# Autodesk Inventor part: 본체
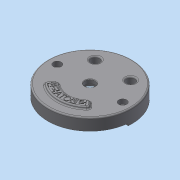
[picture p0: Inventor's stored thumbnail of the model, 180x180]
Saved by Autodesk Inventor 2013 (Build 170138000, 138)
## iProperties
Created: 2015-04
Part Number: 본체
Material: 일반
Document SubType Name: Modeling
Designer: Administrator
Density: 1 g/cm^3
Author: Administrator
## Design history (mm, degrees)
sketch "스케치1"
  geometry: C1 r 95 at (0, 0); 1 further point
  constraints: 1 centre point, 1 coincident
  dimensions: "d0" = 190 diameter of C1
extrude "돌출1" new body sketch "스케치1" distance "d1" = 32; taper "d2" = 0 deg
feature "쉘1" dims "d3" = 14, "d4" = 5
sketch "스케치2"
  geometry: C1 r 90 at (0, 0) reference; C2 r 35 at (0, 0)
  constraints: 1 centre point, 1 coincident
  dimensions: "d5" = 70 diameter of C2
extrude "돌출2" join sketch "스케치2" distance "d6" = 10; taper "d7" = -10 deg
sketch "스케치3"
  geometry: C1 r 35 at (0, 0) reference; A1 r 41 centre (0, -19) between (-40.794, -14.9) and (40.794, -14.9); A2 r 59 centre (0, -19) between (-58.704, -13.1) and (58.704, -13.1); A3 r 9 centre (-49.749, -14) between (-40.794, -14.9) and (-58.704, -13.1); A4 r 9 centre (49.749, -14) between (58.704, -13.1) and (40.794, -14.9)
  constraints: 8 point on circle, 4 centre point, 2 tangent, 1 coincident, 1 vertical alignment
  dimensions: "d8" = 82 diameter of A1; "d9" = 19 distance of A1.centre C1.centre; "d10" = 118 diameter of A2; "d11" = 18 diameter of A3; "d12" = 18 diameter of A4; "d13" = 14 vertical distance of C1.centre A3.centre; "d14" = 14 vertical distance of C1.centre A4.centre
extrude "돌출3" cut sketch "스케치3" distance "d15" = 7; taper "d16" = 0 deg
sketch "스케치4"
  geometry: L1 (-89.196, 12)-(-40.249, 12); L2 (40.249, 12)-(89.196, 12); C1 r 35 at (0, 0) reference; A1 r 90 centre (0, 0) between (89.196, 12) and (-89.196, 12) reference; A2 r 42 centre (0, 0) between (40.249, 12) and (-40.249, 12)
  constraints: 4 end point, 4 point on circle, 2 horizontal, 1 centre point, 1 coincident
  dimensions: "d17" = 84 diameter of A2; "d19" = 12 distance from line of C1.centre L1; "d20" = 12 distance from line of C1.centre L2
extrude "돌출4" cut sketch "스케치4" distance "d21" = 7; taper "d22" = 0 deg
fillet "모깎기1" dims "d23" = 10
sketch "스케치5"
  geometry: C1 r 95 at (0, 0) reference; C2 r 15 at (-40, 52); C3 r 9 at (-74, 0)
  constraints: 2 centre point, 1 horizontal alignment
  dimensions: "d24" = 30 diameter of C2; "d25" = 18 diameter of C3; "d26" = 52 vertical distance of C1.centre C2.centre; "d27" = 40 horizontal distance of C1.centre C2.centre; "d28" = 74 distance of C1.centre C3.centre
extrude "돌출5" join sketch "스케치5" distance "d29" = 32; taper "d30" = 0 deg
sketch "스케치6"
  geometry: C1 r 15 at (0, 0) reference; C2 r 10 at (0, 0); 1 further point
  constraints: 1 centre point, 1 coincident
  dimensions: "d31" = 20 diameter of C2
extrude "돌출6" cut sketch "스케치6" stored distance "d32" = 32; taper "d33" = 0 deg
sketch "스케치7"
  geometry: C1 r 9 at (-74, 0) reference
hole "구멍1" sketch "스케치7" at (-74, 0) diameter "d34" = 11; stored, may be unused: countersink angle "d38" = 90 deg, drill point angle "d40" = 118 deg; dims "d35" = 6, "d36" = 18, "d37" = 11, "d39" = 8
sketch "스케치8"
  geometry: L1 (-20, 6)-(20, 6); L2 (20, 6)-(20, -6); L3 (20, -6)-(-20, -6); L4 (-20, -6)-(-20, 6); L5 (-86, 20)-(-74, 20); L6 (-74, 20)-(-74, -20); L7 (-74, -20)-(-86, -20); L8 (-86, -20)-(-86, 20); C1 r 10 at (0, 0) reference; C2 r 10 at (-80, 0) reference; C3 r 15 at (-80, 0) reference; 5 further points
  constraints: 16 end point, 4 midpoint, 4 parallel, 2 horizontal, 2 horizontal alignment, 2 perpendicular, 2 vertical alignment
  dimensions: "d41" = 12 distance of L3.end L1.start; "d43" = 12 distance of L5.start L5.end; "d44" = 40 distance of L1.start L1.end; "d45" = 40 distance of L5.end L6.end
extrude "돌출7" cut sketch "스케치8" distance "d46" = 3; taper "d47" = 0 deg
sketch "스케치9"
  geometry: C1 r 33.237 at (0, 0) reference
hole "구멍2" sketch "스케치9" at (0, 0) diameter "d48" = 23; stored, may be unused: countersink angle "d52" = 90 deg, drill point angle "d54" = 118 deg; dims "d49" = 6, "d50" = 50, "d51" = 15, "d53" = 8
chamfer "모따기1" distance "d55" = 1; stored, may be unused: second distance "d56" = 2, angle "d57" = 45 deg
fillet "모깎기2" dims "d58" = 3
node "작업 평면1"
sketch "스케치10"
  geometry: L1 (-89.658, -7.844)-(-101.855, -8.911); L2 (89.658, -7.844)-(101.855, -8.911); L3 (-74, 0)-(74, 0); C1 r 95 at (0, 0) reference; C2 r 10 at (40, 52) reference; C3 r 10 at (-40, 52) reference; C4 r 15 at (40, 52) reference; C5 r 15 at (-40, 52) reference; C6 r 5.5 at (74, 0) reference; C7 r 9 at (74, 0) reference; C8 r 5.5 at (-74, 0) reference; C9 r 9 at (-74, 0) reference; A1 r 90 centre (0, 0) between (-89.658, -7.844) and (89.658, -7.844) reference; A2 r 102.244 centre (0, 0) between (-101.855, -8.911) and (101.855, -8.911); A3 r 90 centre (0, 0) between (-89.658, -7.844) and (89.658, -7.844); 1 further point
  constraints: 6 end point, 6 point on circle, 2 centre point, 2 coincident, 1 concentric, 1 horizontal
  dimensions: "d62" = 204.48899 diameter of A2; "d63" = 5 deg angle of L1 L3; "d64" = 5 deg angle of L2 L3; "d65" = 7.84402 vertical distance of L1.start C8.centre; "d66" = 7.84402 vertical distance of L2.start C6.centre
extrude "돌출8" cut sketch "스케치10" distance "d67" = 5; taper "d68" = 0 deg
fillet "모깎기3" dims "d69" = 3
sketch "스케치11"
  geometry: L1 (-72, 0)-(0, 0); L2 (36.062, -36.062)-(50.912, -50.912); L3 (-36.062, -36.062)-(-50.912, -50.912); C1 r 12.5 at (0, 0) reference; C2 r 92 at (0, 0) reference; A1 r 51 centre (0, 0) between (-36.062, -36.062) and (36.062, -36.062); A2 r 72 centre (0, 0) between (-50.912, -50.912) and (50.912, -50.912); A3 r 72 centre (0, 0) between (-50.912, 50.912) and (-52.67, 49.09); 1 further point
  constraints: 6 end point, 6 point on circle, 3 centre point, 2 coincident, 1 horizontal, 1 point on line, 2 other
  dimensions: "d71" = 102 diameter of A1; "d74" = 45 deg angle of L3 L1; "d75" = 90 deg angle of L2 L3; "d77" = 72 radius of A2; "d78" = 36.06245 horizontal distance of L3.start C1.centre; "d79" = 36.06245 horizontal distance of L2.start C1.centre
extrude "돌출9" join sketch "스케치11" distance "d80" = 5; taper "d81" = 0 deg
fillet "모깎기4" dims "d82" = 5
fillet "모깎기5" dims "d83" = 3
sketch "스케치12"
  geometry: C1 r 68 at (0, 0); 1 further point
  constraints: 1 centre point, 1 coincident, 1 other
  dimensions: "d85" = 136 diameter of C1
feature "엠보싱1" sketch "스케치12" dims "d8" = 82, "d9" = 19, "d10" = 118, "d11" = 18, "d12" = 18, "d13" = 14, "d14" = 14, "d86" = 0.5, "d87" = 0
fillet "모깎기7" dims "d88" = 3
fillet "모깎기8" dims "d89" = 0.3
fillet "모깎기9" dims "d90" = 1
node "솔리드1"
mirror "대칭1"
node "투영된 루프1"
node "절단 모서리 투영1"
other parameters: "d18" = 12, "d59" = 5, "d70" = 144, "d72" = 90 deg, "d73" = 45 deg
